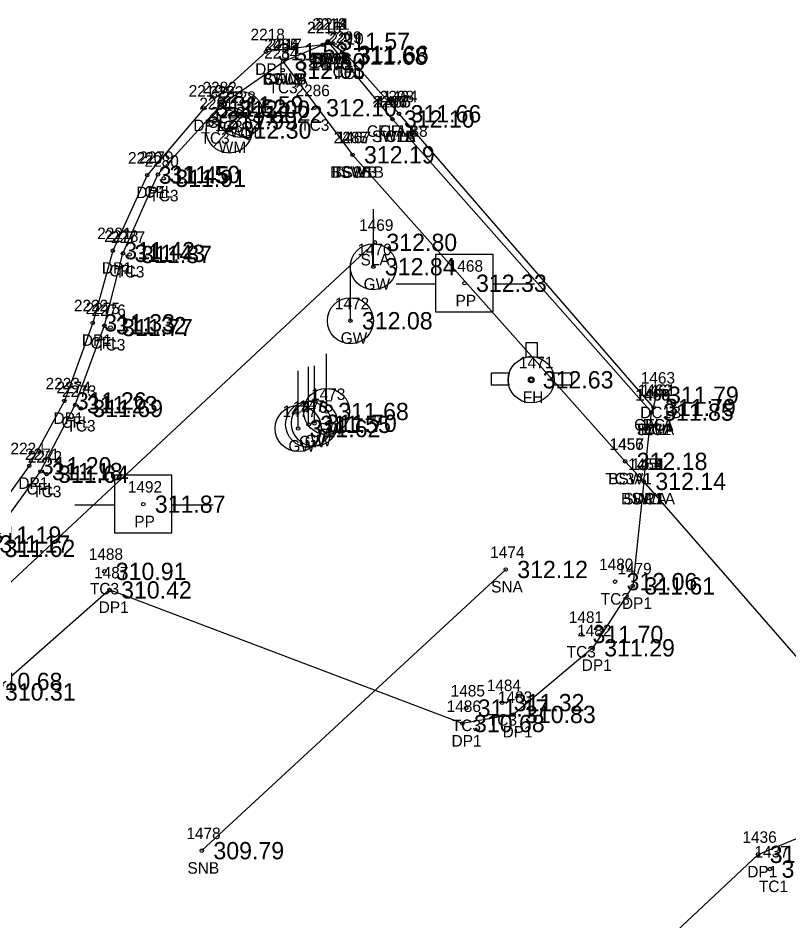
# Model space of a CAD drawing. Extents: x 1970076 to 1971136, y 803126 to 804215.
# Drawn here: x 1970397.9 to 1970464.7, y 803647.8 to 803726.1 of the extents above; entities that cross this region are included whole.
import ezdxf

# ---------------------------------------------------------------- set-up
doc = ezdxf.new("R2010")
doc.units = 0
for name, color, linetype in [('RD_EX_BldgApp', 7, 'Continuous'), ('RD_EX_BldgApp_txCode', 7, 'Continuous'), ('RD_EX_Conc', 7, 'Continuous'), ('RD_EX_Conc_txCode', 7, 'Continuous'), ('RD_EX_Driveway', 7, 'Continuous'), ('RD_EX_Driveway_txCode', 7, 'Continuous'), ('RD_EX_TX_BldgApp_ELEV', 7, 'Continuous'), ('RD_EX_TX_Conc_ELEV', 7, 'Continuous'), ('RD_EX_TX_Driveway_ELEV', 7, 'Continuous'), ('RD_EX_TX_UT_ELEV', 7, 'Continuous'), ('RD_EX_TX_VEG_ELEV', 7, 'Continuous'), ('RD_EX_UT', 7, 'Continuous'), ('RD_EX_UT_txCode', 7, 'Continuous'), ('RD_EX_VEG', 7, 'Continuous'), ('RD_EX_VEG_txCode', 7, 'Continuous'), ('RD_HC_Survey_ELEV', 7, 'Continuous'), ('RD_SMD_Locator', 7, 'Continuous')]:
    doc.layers.add(name, color=color, linetype=linetype)

msp = doc.modelspace()

# ---------------------------------------------------------------- linework, layer by layer
at = {"layer": 'RD_EX_BldgApp'}
msp.add_line((1970440.161, 803678.265), (1970413.799, 803653.863), dxfattribs=at)
at = {"layer": 'RD_EX_Conc'}
for p, q in [((1970420.848, 803722.328), (1970426.863, 803714.251)), ((1970452.988, 803692.319), (1970430.904, 803717.807))]:
    msp.add_line(p, q, dxfattribs=at)
for points in [[(1970430.328, 803717.353), (1970424.723, 803724.099), (1970424.286, 803723.788), (1970420.848, 803722.328)], [(1970430.904, 803717.807), (1970426.347, 803722.96), (1970424.723, 803724.099)], [(1970378.91, 803665.388), (1970390.009, 803675.178), (1970395.241, 803680.476), (1970399.794, 803686.756), (1970402.816, 803692.555), (1970405.342, 803699.423), (1970406.952, 803705.695), (1970409.991, 803712.539), (1970415.481, 803718.584), (1970420.848, 803722.328)], [(1970452.137, 803685.907), (1970452.812, 803691.92), (1970430.328, 803717.353)], [(1970452.137, 803685.907), (1970450.528, 803687.644), (1970426.863, 803714.251)], [(1970478.911, 803655.171), (1970452.137, 803685.907), (1970452.812, 803691.92), (1970452.988, 803692.319), (1970453.247, 803693.391)]]:
    msp.add_lwpolyline(points, dxfattribs=at)
at = {"layer": 'RD_EX_Driveway'}
for points in [[(1970424.723, 803724.099), (1970424.286, 803723.788), (1970419.367, 803723.185), (1970414, 803718.301), (1970409.058, 803712.485), (1970406.065, 803705.927), (1970404.327, 803699.669), (1970401.865, 803692.891), (1970398.82, 803687.26), (1970394.468, 803681.254), (1970389.336, 803675.913), (1970378.274, 803666.142)], [(1970511.893, 803542.412), (1970514.792, 803545.038), (1970514.012, 803573.46), (1970523.859, 803581.554), (1970466.06, 803647.507), (1970457.368, 803639.418), (1970456.639, 803639.958), (1970456.168, 803640.482), (1970453.444, 803643.559), (1970453.189, 803643.898), (1970452.573, 803644.606), (1970462.065, 803653.541), (1970470.49, 803657.022), (1970478.911, 803655.171), (1970478.911, 803655.171), (1970452.137, 803685.907), (1970452.137, 803685.907), (1970451.191, 803676.836), (1970447.704, 803671.466), (1970440.833, 803665.684), (1970436.405, 803664.894), (1970405.792, 803676.487), (1970395.71, 803667.638)]]:
    msp.add_lwpolyline(points, dxfattribs=at)
at = {"layer": 'RD_EX_UT'}
for p, q in [((1970415.78, 803716.295), (1970418.447, 803719.192)), ((1970415.299, 803718.591), (1970418.929, 803716.878)), ((1970414.816, 803714.941), (1970417.483, 803717.837)), ((1970414.334, 803717.236), (1970417.965, 803715.523)), ((1970428.675, 803704.535), (1970428.675, 803709.535)), ((1970439.078, 803705.61), (1970434.078, 803705.61)), ((1970434.078, 803705.61), (1970434.078, 803700.61)), ((1970439.078, 803700.61), (1970439.078, 803705.61)), ((1970426.684, 803699.85), (1970426.684, 803704.85)), ((1970430.647, 803703.047), (1970434.116, 803703.047)), ((1970439.006, 803703.047), (1970442.647, 803703.047)), ((1970434.078, 803700.61), (1970439.078, 803700.61)), ((1970441.916, 803697.943), (1970441.916, 803696.67)), ((1970442.916, 803697.943), (1970441.916, 803697.943)), ((1970442.916, 803696.647), (1970442.916, 803697.943)), ((1970424.617, 803691.973), (1970424.617, 803696.973)), ((1970423.063, 803690.856), (1970423.063, 803695.856)), ((1970423.572, 803690.948), (1970423.572, 803695.948)), ((1970422.15, 803690.492), (1970422.15, 803695.492)), ((1970440.457, 803695.296), (1970438.899, 803695.296)), ((1970438.899, 803695.296), (1970438.899, 803694.296)), ((1970445.899, 803695.296), (1970444.289, 803695.296)), ((1970445.899, 803694.296), (1970445.899, 803695.296)), ((1970438.899, 803694.296), (1970440.419, 803694.296)), ((1970444.327, 803694.296), (1970445.899, 803694.296)), ((1970411.206, 803686.438), (1970406.206, 803686.438)), ((1970406.206, 803686.438), (1970406.206, 803681.438)), ((1970411.206, 803681.438), (1970411.206, 803686.438)), ((1970402.775, 803683.876), (1970406.244, 803683.876)), ((1970411.134, 803683.876), (1970414.775, 803683.876)), ((1970406.206, 803681.438), (1970411.206, 803681.438))]:
    msp.add_line(p, q, dxfattribs=at)
for centre, radius in [((1970417.132, 803717.753), 2), ((1970416.168, 803716.399), 2), ((1970428.675, 803704.535), 1.999), ((1970426.684, 803699.85), 1.999), ((1970442.373, 803694.723), 2), ((1970442.373, 803694.723), 0.25), ((1970424.617, 803691.973), 1.999), ((1970422.15, 803690.492), 1.999), ((1970423.063, 803690.856), 1.999), ((1970423.572, 803690.948), 1.999)]:
    msp.add_circle(centre, radius, dxfattribs=at)
for start, end in [(74.24553, 103.21276), (163.3387, 192.31502), (347.68498, 16.6613)]:
    msp.add_arc((1970442.373, 803694.723), 2, start, end, dxfattribs=at)
at = {"layer": 'RD_EX_VEG'}
msp.add_line((1970428.809, 803706.649), (1970389.584, 803670.063), dxfattribs=at)
at = {"layer": 'RD_SMD_Locator'}
for centre in [(1970424.286, 803723.788), (1970424.286, 803723.788), (1970424.723, 803724.099), (1970424.723, 803724.099), (1970424.723, 803724.099), (1970424.723, 803724.099), (1970419.367, 803723.185), (1970426.347, 803722.96), (1970420.848, 803722.328), (1970420.848, 803722.328), (1970420.848, 803722.328), (1970426.245, 803722.819), (1970420.824, 803721.585), (1970414, 803718.301), (1970415.481, 803718.584), (1970416.055, 803718.203), (1970423.575, 803718.331), (1970417.132, 803717.753), (1970430.904, 803717.807), (1970430.904, 803717.807), (1970414.925, 803717.207), (1970430.328, 803717.353), (1970430.328, 803717.353), (1970430.328, 803717.353), (1970430.328, 803717.353), (1970416.168, 803716.399), (1970426.863, 803714.251), (1970426.863, 803714.251), (1970426.863, 803714.251), (1970409.058, 803712.485), (1970409.991, 803712.539), (1970410.49, 803712.205), (1970428.809, 803706.649), (1970406.065, 803705.927), (1970406.952, 803705.695), (1970407.531, 803705.598), (1970428.675, 803704.535), (1970436.587, 803703.101), (1970404.327, 803699.669), (1970405.342, 803699.423), (1970426.684, 803699.85), (1970405.875, 803699.259), (1970442.373, 803694.723), (1970453.247, 803693.391), (1970401.865, 803692.891), (1970402.816, 803692.555), (1970452.988, 803692.319), (1970452.988, 803692.319), (1970403.291, 803692.236), (1970424.617, 803691.973), (1970452.812, 803691.92), (1970452.812, 803691.92), (1970452.812, 803691.92), (1970423.063, 803690.856), (1970423.572, 803690.948), (1970422.15, 803690.492), (1970450.528, 803687.644), (1970450.528, 803687.644), (1970398.82, 803687.26), (1970399.794, 803686.756), (1970400.325, 803686.529), (1970452.137, 803685.907), (1970452.137, 803685.907), (1970452.137, 803685.907), (1970452.137, 803685.907), (1970452.137, 803685.907), (1970408.715, 803683.929), (1970440.161, 803678.265), (1970405.329, 803678.098), (1970449.648, 803677.207), (1970451.191, 803676.836), (1970405.792, 803676.487), (1970446.694, 803672.623), (1970447.704, 803671.466), (1970439.856, 803666.708), (1970436.729, 803666.238), (1970440.833, 803665.684), (1970436.405, 803664.894), (1970413.799, 803653.863), (1970462.065, 803653.541), (1970463.088, 803652.267)]:
    msp.add_circle(centre, 0.15, dxfattribs=at)

# ---------------------------------------------------------------- texts
at = {"layer": 'RD_EX_BldgApp_txCode'}
for s, p in [('1474', (1970438.815, 803679.265)), ('SNA', (1970438.893, 803676.265)), ('1478', (1970412.452, 803654.863)), ('SNB', (1970412.547, 803651.863))]:
    msp.add_text(s, height=1, dxfattribs=at).set_placement(p)
at = {"layer": 'RD_EX_Conc_txCode'}
for s, p in [('2216', (1970422.916, 803724.788)), ('2212', (1970423.377, 803725.099)), ('2213', (1970423.377, 803725.099)), ('2211', (1970423.66, 803725.099)), ('2209', (1970424.678, 803723.96)), ('2210', (1970424.859, 803723.819)), ('2285', (1970419.218, 803723.328)), ('2434', (1970419.218, 803723.328)), ('2217', (1970419.502, 803723.328)), ('2284', (1970419.194, 803722.585)), ('CFLB', (1970423.046, 803722.099)), ('TC1B', (1970423.29, 803722.099)), ('SWL', (1970423.432, 803722.099)), ('SWL', (1970422.995, 803721.788)), ('CFL', (1970425.142, 803720.96)), ('TC1', (1970425.284, 803720.819)), ('SWLB', (1970419.085, 803720.328)), ('BSWA', (1970419.045, 803720.328)), ('CFLB', (1970419.171, 803720.328)), ('2282', (1970413.851, 803719.584)), ('2283', (1970414.425, 803719.203)), ('TC3', (1970419.58, 803719.585)), ('2286', (1970421.922, 803719.331)), ('2281', (1970413.578, 803718.207)), ('2206', (1970428.635, 803718.353)), ('2207', (1970428.659, 803718.353)), ('1466', (1970428.934, 803718.353)), ('1465', (1970428.958, 803718.353)), ('2208', (1970429.235, 803718.807)), ('1464', (1970429.534, 803718.807)), ('CFL', (1970414.277, 803716.584)), ('TC3', (1970414.811, 803716.203)), ('TC3', (1970422.331, 803716.331)), ('CFLA 18', (1970428.109, 803715.807)), ('CFLB', (1970429.227, 803715.807)), ('TC3', (1970413.681, 803715.207)), ('2287', (1970425.233, 803715.251)), ('2435', (1970425.233, 803715.251)), ('1467', (1970425.493, 803715.251)), ('SWLA', (1970428.549, 803715.353)), ('SWLB', (1970428.564, 803715.353)), ('TC1A', (1970428.879, 803715.353)), ('TC1B', (1970428.895, 803715.353)), ('2279', (1970408.361, 803713.539)), ('2280', (1970408.821, 803713.205)), ('BSW1B', (1970424.911, 803712.251)), ('TC3B', (1970425.147, 803712.251)), ('BSWB', (1970425.076, 803712.251)), ('CFL', (1970408.787, 803710.539)), ('TC3', (1970409.246, 803710.205)), ('2278', (1970405.322, 803706.695)), ('2277', (1970405.901, 803706.598)), ('CFL', (1970405.747, 803703.695)), ('TC3', (1970406.287, 803703.598)), ('2275', (1970403.712, 803700.423)), ('2276', (1970404.221, 803700.259)), ('CFL', (1970404.137, 803697.423)), ('TC3', (1970404.631, 803697.259)), ('1463', (1970451.876, 803694.391)), ('2274', (1970401.186, 803693.555)), ('2273', (1970401.661, 803693.236)), ('1462', (1970451.618, 803693.319)), ('1461', (1970451.901, 803693.319)), ('1460', (1970451.402, 803692.92)), ('1458', (1970451.465, 803692.92)), ('1459', (1970451.465, 803692.92)), ('DC1B', (1970451.829, 803691.391)), ('CFL', (1970401.611, 803690.555)), ('TC3', (1970402.047, 803690.236)), ('CFLA', (1970451.295, 803690.319)), ('TC1A', (1970451.363, 803689.92)), ('SWL', (1970451.52, 803689.92)), ('DC1', (1970451.867, 803689.92)), ('DC1', (1970452.043, 803690.319)), ('1456', (1970449.158, 803688.644)), ('1457', (1970449.182, 803688.644)), ('2271', (1970398.448, 803687.756)), ('2272', (1970398.695, 803687.529)), ('1453', (1970450.79, 803686.907)), ('1454', (1970450.79, 803686.907)), ('1455', (1970450.79, 803686.907)), ('TC3A', (1970448.796, 803685.644)), ('BSW1', (1970449.048, 803685.644)), ('CFL', (1970398.59, 803684.756)), ('TC3', (1970399.081, 803684.529)), ('BSW1A', (1970450.168, 803683.907)), ('SWLA', (1970450.357, 803683.907)), ('DC1', (1970451.192, 803683.907)), ('1488', (1970403.982, 803679.098)), ('1480', (1970448.262, 803678.207)), ('TC3', (1970404.085, 803676.098)), ('TC3', (1970448.404, 803675.207)), ('1481', (1970445.631, 803673.623)), ('TC3', (1970445.45, 803670.623)), ('1485', (1970435.382, 803667.238)), ('1484', (1970438.509, 803667.708)), ('TC3', (1970435.484, 803664.238)), ('TC3', (1970438.612, 803664.708)), ('1437', (1970461.742, 803653.267)), ('TC1', (1970462.127, 803650.267))]:
    msp.add_text(s, height=1, dxfattribs=at).set_placement(p)
at = {"layer": 'RD_EX_Driveway_txCode'}
for s, p in [('2215', (1970422.94, 803724.788)), ('2214', (1970423.377, 803725.099)), ('2218', (1970418.02, 803724.185)), ('DP1A', (1970423.29, 803722.099)), ('DP1', (1970423.341, 803721.788)), ('DP1', (1970418.422, 803721.185)), ('2219', (1970412.654, 803719.301)), ('DP1', (1970413.055, 803716.301)), ('2220', (1970407.389, 803713.485)), ('DP1', (1970408.113, 803710.485)), ('2221', (1970404.718, 803706.927)), ('DP1', (1970405.12, 803703.927)), ('2222', (1970402.697, 803700.669)), ('DP1', (1970403.382, 803697.669)), ('2223', (1970400.235, 803693.891)), ('DP1', (1970400.92, 803690.891)), ('2224', (1970397.19, 803688.26)), ('1452', (1970450.79, 803686.907)), ('1451', (1970451.074, 803686.907)), ('DP1', (1970397.875, 803685.26)), ('DP1', (1970451.192, 803683.907)), ('DP1', (1970451.192, 803683.907)), ('1487', (1970404.445, 803677.487)), ('1479', (1970449.845, 803677.836)), ('DP1', (1970404.847, 803674.487)), ('DP1', (1970450.246, 803674.836)), ('1482', (1970446.358, 803672.466)), ('DP1', (1970446.759, 803669.466)), ('1483', (1970439.486, 803666.684)), ('1486', (1970435.035, 803665.894)), ('DP1', (1970439.888, 803663.684)), ('DP1', (1970435.46, 803662.894)), ('1436', (1970460.695, 803654.541)), ('DP1', (1970461.12, 803651.541))]:
    msp.add_text(s, height=1, dxfattribs=at).set_placement(p)
at = {"layer": 'RD_EX_TX_BldgApp_ELEV'}
for s, p in [('312.12', (1970441.161, 803677.515)), ('309.79', (1970414.799, 803653.113))]:
    msp.add_text(s, height=1.5, dxfattribs=at).set_placement(p)
at = {"layer": 'RD_EX_TX_Conc_ELEV'}
for s, p in [('311.57', (1970425.723, 803723.349)), ('311.57', (1970425.723, 803723.349)), ('311.57', (1970425.723, 803723.349)), ('311.56', (1970425.286, 803723.038)), ('311.60', (1970421.848, 803721.578)), ('311.60', (1970421.848, 803721.578)), ('311.60', (1970421.848, 803721.578)), ('311.68', (1970427.245, 803722.069)), ('311.66', (1970427.347, 803722.21)), ('312.03', (1970421.824, 803720.835)), ('311.59', (1970416.481, 803717.834)), ('312.10', (1970424.575, 803717.581)), ('312.00', (1970417.055, 803717.453)), ('311.66', (1970431.904, 803717.057)), ('311.66', (1970431.904, 803717.057)), ('311.99', (1970415.925, 803716.457)), ('312.10', (1970431.328, 803716.603)), ('312.10', (1970431.328, 803716.603)), ('312.10', (1970431.328, 803716.603)), ('312.10', (1970431.328, 803716.603)), ('312.19', (1970427.863, 803713.501)), ('312.19', (1970427.863, 803713.501)), ('312.19', (1970427.863, 803713.501)), ('311.50', (1970410.991, 803711.789)), ('311.91', (1970411.49, 803711.455)), ('311.43', (1970407.952, 803704.945)), ('311.87', (1970408.531, 803704.848)), ('311.32', (1970406.342, 803698.673)), ('311.77', (1970406.875, 803698.509)), ('311.79', (1970454.247, 803692.641)), ('311.23', (1970403.816, 803691.805)), ('311.69', (1970404.291, 803691.486)), ('311.85', (1970453.812, 803691.17)), ('311.85', (1970453.812, 803691.17)), ('311.85', (1970453.812, 803691.17)), ('311.79', (1970453.988, 803691.569)), ('311.79', (1970453.988, 803691.569)), ('312.18', (1970451.528, 803686.894)), ('312.18', (1970451.528, 803686.894)), ('311.18', (1970400.794, 803686.006)), ('311.64', (1970401.325, 803685.779)), ('312.14', (1970453.137, 803685.157)), ('312.14', (1970453.137, 803685.157)), ('312.14', (1970453.137, 803685.157)), ('311.17', (1970396.241, 803679.726)), ('311.62', (1970396.677, 803679.345)), ('310.91', (1970406.329, 803677.348)), ('312.06', (1970450.648, 803676.457)), ('311.70', (1970447.694, 803671.873)), ('310.68', (1970395.564, 803667.8)), ('311.32', (1970440.856, 803665.958)), ('311.17', (1970437.729, 803665.488)), ('311.59', (1970464.088, 803651.517))]:
    msp.add_text(s, height=1.5, dxfattribs=at).set_placement(p)
at = {"layer": 'RD_EX_TX_Driveway_ELEV'}
for s, p in [('311.57', (1970425.723, 803723.349)), ('311.53', (1970420.367, 803722.435)), ('311.56', (1970425.286, 803723.038)), ('311.52', (1970415, 803717.551)), ('311.45', (1970410.058, 803711.735)), ('311.42', (1970407.065, 803705.177)), ('311.33', (1970405.327, 803698.919)), ('311.26', (1970402.865, 803692.141)), ('311.20', (1970399.82, 803686.51)), ('312.14', (1970453.137, 803685.157)), ('312.14', (1970453.137, 803685.157)), ('311.19', (1970395.468, 803680.504)), ('311.61', (1970452.191, 803676.086)), ('310.42', (1970406.792, 803675.737)), ('311.29', (1970448.704, 803670.716)), ('310.31', (1970396.71, 803666.888)), ('310.83', (1970441.833, 803664.934)), ('310.68', (1970437.405, 803664.144)), ('311.13', (1970463.065, 803652.791))]:
    msp.add_text(s, height=1.5, dxfattribs=at).set_placement(p)
at = {"layer": 'RD_EX_TX_UT_ELEV'}
for s, p in [('312.22', (1970418.132, 803717.003)), ('312.30', (1970417.168, 803715.649)), ('312.84', (1970429.675, 803703.785)), ('312.08', (1970427.684, 803699.1)), ('312.63', (1970443.373, 803693.973)), ('311.68', (1970425.617, 803691.223)), ('311.70', (1970424.572, 803690.198)), ('311.62', (1970423.15, 803689.742)), ('311.55', (1970424.063, 803690.106))]:
    msp.add_text(s, height=1.5, dxfattribs=at).set_placement(p)
at = {"layer": 'RD_EX_TX_VEG_ELEV'}
msp.add_text('312.80', height=1.5, dxfattribs=at).set_placement((1970429.809, 803705.899))
at = {"layer": 'RD_EX_UT_txCode'}
for s, p in [('2228', (1970415.502, 803718.753)), ('2229', (1970414.538, 803717.399)), ('WM', (1970416.227, 803715.753)), ('WM', (1970415.262, 803714.399)), ('1470', (1970427.289, 803705.535)), ('1468', (1970435.217, 803704.101)), ('GW', (1970427.832, 803702.535)), ('1472', (1970425.337, 803700.85)), ('PP', (1970435.807, 803701.101)), ('GW', (1970425.841, 803697.85)), ('1471', (1970441.31, 803695.723)), ('1473', (1970423.271, 803692.973)), ('FH', (1970441.641, 803692.723)), ('1477', (1970420.803, 803691.492)), ('1476', (1970421.693, 803691.856)), ('1475', (1970422.225, 803691.948)), ('GW', (1970423.775, 803689.973)), ('GW', (1970421.307, 803688.492)), ('GW', (1970422.22, 803688.856)), ('GW', (1970422.729, 803688.948)), ('1492', (1970407.368, 803684.929)), ('PP', (1970407.935, 803681.929))]:
    msp.add_text(s, height=1, dxfattribs=at).set_placement(p)
at = {"layer": 'RD_EX_VEG_txCode'}
for s, p in [('1469', (1970427.439, 803707.649)), ('SLA', (1970427.565, 803704.649))]:
    msp.add_text(s, height=1, dxfattribs=at).set_placement(p)
at = {"layer": 'RD_HC_Survey_ELEV'}
for s, p in [('312.33', (1970437.587, 803702.351)), ('311.87', (1970409.715, 803683.179))]:
    msp.add_text(s, height=1.5, dxfattribs=at).set_placement(p)

doc.saveas('drawing.dxf')
